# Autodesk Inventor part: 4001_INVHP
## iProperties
Company: Wekoplan
Created: 2005-03
Part Number: 4001_INVHP
Document SubType Name: Modeling
Designer: Schröther
Manufacturer: Standard
Standards Organization: Custom
Author: Schröther
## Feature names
1. Extrusion1
2. Extrusion2
3. Erhebung1
4. Erhebung2
5. Erhebung3
6. Erhebung4
